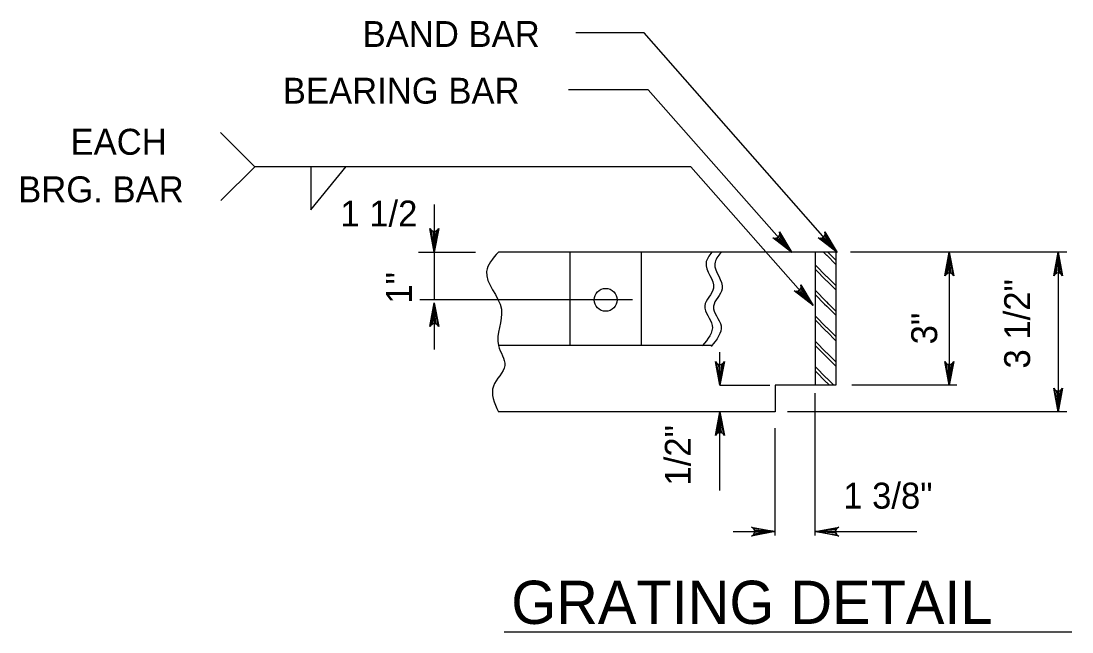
# Model space of a CAD drawing. Extents: x -0.3 to 6.9, y -6.5 to 3.5.
# Drawn here: x 3.745 to 6.178, y -4.783 to -3.37 of the extents above; entities that cross this region are included whole.
import ezdxf

# ---------------------------------------------------------------- set-up
doc = ezdxf.new("R2010")
doc.units = 0
for name, color, linetype in [('DETL-DIMS', 7, 'Continuous'), ('DETL-LINE', 7, 'Continuous'), ('DETL-NOTE', 7, 'Continuous'), ('DETL-PATT', 7, 'Continuous'), ('DETL-TITL', 7, 'Continuous')]:
    doc.layers.add(name, color=color, linetype=linetype)

msp = doc.modelspace()

# ---------------------------------------------------------------- linework, layer by layer
at = {"layer": 'DETL-DIMS'}
for p, q in [((5.188, -3.3971), (5.0297, -3.3971)), ((5.6347, -3.9053), (5.188, -3.3971)), ((5.1968, -3.5285), (5.0123, -3.5285)), ((5.5296, -3.9053), (5.1968, -3.5285)), ((4.2859, -3.7067), (4.2066, -3.6274)), ((4.2859, -3.7067), (4.2074, -3.7852)), ((5.296, -3.7067), (4.2859, -3.7067)), ((4.4154, -3.8066), (4.4978, -3.7065)), ((4.4154, -3.7067), (4.4154, -3.8066)), ((5.5792, -4.028), (5.296, -3.7067)), ((4.7016, -3.7941), (4.7016, -3.9044)), ((4.6654, -3.9044), (4.7968, -3.9044)), ((4.7016, -3.9044), (4.7016, -4.0147)), ((6.1668, -3.9044), (5.6655, -3.9044)), ((5.8942, -3.9044), (5.8942, -4.2124)), ((6.1463, -3.9044), (6.1463, -4.2737)), ((5.1605, -4.0147), (4.6681, -4.0147)), ((4.7016, -4.0218), (4.7016, -4.13)), ((5.3632, -4.2124), (5.3632, -4.1361)), ((5.3632, -4.2124), (5.4785, -4.2124)), ((5.5833, -4.5597), (5.5833, -4.231)), ((5.9116, -4.2124), (5.6686, -4.2124)), ((5.3632, -4.456), (5.3632, -4.2737)), ((6.1668, -4.2737), (5.5197, -4.2737)), ((5.4914, -4.5597), (5.4914, -4.3114)), ((5.3938, -4.5509), (5.4914, -4.5509)), ((5.5833, -4.5509), (5.8191, -4.5509))]:
    msp.add_line(p, q, dxfattribs=at)
for points in [[(4.7016, -3.9044), (4.6914, -3.8496), (4.6943, -3.8538), (4.698, -3.856), (4.7016, -3.8566), (4.7053, -3.856), (4.709, -3.8538), (4.7119, -3.8496), (4.7016, -3.9044), (4.709, -3.8538), (4.7053, -3.856), (4.7016, -3.9044), (4.7016, -3.8566), (4.698, -3.856), (4.7016, -3.9044), (4.6943, -3.8538)], [(5.5296, -3.9053), (5.4856, -3.8711), (5.4906, -3.8723), (5.4947, -3.8715), (5.4979, -3.8695), (5.5003, -3.8666), (5.5016, -3.8625), (5.501, -3.8574), (5.5296, -3.9053), (5.5016, -3.8625), (5.5003, -3.8666), (5.5296, -3.9053), (5.4979, -3.8695), (5.4947, -3.8715), (5.5296, -3.9053), (5.4906, -3.8723)], [(5.6347, -3.9053), (5.5907, -3.8709), (5.5957, -3.8722), (5.5999, -3.8714), (5.6031, -3.8694), (5.6055, -3.8665), (5.6068, -3.8625), (5.6062, -3.8574), (5.6347, -3.9053), (5.6068, -3.8625), (5.6055, -3.8665), (5.6347, -3.9053), (5.6031, -3.8694), (5.5999, -3.8714), (5.6347, -3.9053), (5.5957, -3.8722)], [(5.8942, -3.9044), (5.9045, -3.9592), (5.9016, -3.955), (5.8979, -3.9528), (5.8942, -3.9522), (5.8906, -3.9528), (5.8869, -3.955), (5.8839, -3.9592), (5.8942, -3.9044), (5.8869, -3.955), (5.8906, -3.9528), (5.8942, -3.9044), (5.8942, -3.9522), (5.8979, -3.9528), (5.8942, -3.9044), (5.9016, -3.955)], [(5.8942, -3.9044), (5.9045, -3.9592), (5.9016, -3.955), (5.8979, -3.9528), (5.8942, -3.9522), (5.8906, -3.9528), (5.8869, -3.955), (5.8839, -3.9592), (5.8942, -3.9044), (5.8869, -3.955), (5.8906, -3.9528), (5.8942, -3.9044), (5.8942, -3.9522), (5.8979, -3.9528), (5.8942, -3.9044), (5.9016, -3.955)], [(6.1463, -3.9044), (6.1566, -3.9592), (6.1537, -3.955), (6.15, -3.9528), (6.1463, -3.9522), (6.1427, -3.9528), (6.139, -3.955), (6.1361, -3.9592), (6.1463, -3.9044), (6.139, -3.955), (6.1427, -3.9528), (6.1463, -3.9044), (6.1463, -3.9522), (6.15, -3.9528), (6.1463, -3.9044), (6.1537, -3.955)], [(5.5792, -4.028), (5.5352, -3.9937), (5.5402, -3.9949), (5.5444, -3.9941), (5.5476, -3.9922), (5.5499, -3.9893), (5.5512, -3.9852), (5.5507, -3.9801), (5.5792, -4.028), (5.5512, -3.9852), (5.5499, -3.9893), (5.5792, -4.028), (5.5476, -3.9922), (5.5444, -3.9941), (5.5792, -4.028), (5.5402, -3.9949)], [(4.7016, -4.0218), (4.7119, -4.0766), (4.709, -4.0724), (4.7053, -4.0702), (4.7016, -4.0696), (4.698, -4.0702), (4.6943, -4.0724), (4.6914, -4.0766), (4.7016, -4.0218), (4.6943, -4.0724), (4.698, -4.0702), (4.7016, -4.0218), (4.7016, -4.0696), (4.7053, -4.0702), (4.7016, -4.0218), (4.709, -4.0724)], [(5.3632, -4.2124), (5.3529, -4.1576), (5.3558, -4.1618), (5.3595, -4.164), (5.3632, -4.1646), (5.3668, -4.164), (5.3705, -4.1618), (5.3734, -4.1576), (5.3632, -4.2124), (5.3705, -4.1618), (5.3668, -4.164), (5.3632, -4.2124), (5.3632, -4.1646), (5.3595, -4.164), (5.3632, -4.2124), (5.3558, -4.1618)], [(5.3632, -4.2124), (5.3529, -4.1576), (5.3558, -4.1618), (5.3595, -4.164), (5.3632, -4.1646), (5.3668, -4.164), (5.3705, -4.1618), (5.3734, -4.1576), (5.3632, -4.2124), (5.3705, -4.1618), (5.3668, -4.164), (5.3632, -4.2124), (5.3632, -4.1646), (5.3595, -4.164), (5.3632, -4.2124), (5.3558, -4.1618)], [(5.8942, -4.2124), (5.8839, -4.1576), (5.8869, -4.1618), (5.8906, -4.164), (5.8942, -4.1646), (5.8979, -4.164), (5.9016, -4.1618), (5.9045, -4.1576), (5.8942, -4.2124), (5.9016, -4.1618), (5.8979, -4.164), (5.8942, -4.2124), (5.8942, -4.1646), (5.8906, -4.164), (5.8942, -4.2124), (5.8869, -4.1618)], [(5.8942, -4.2124), (5.8839, -4.1576), (5.8869, -4.1618), (5.8906, -4.164), (5.8942, -4.1646), (5.8979, -4.164), (5.9016, -4.1618), (5.9045, -4.1576), (5.8942, -4.2124), (5.9016, -4.1618), (5.8979, -4.164), (5.8942, -4.2124), (5.8942, -4.1646), (5.8906, -4.164), (5.8942, -4.2124), (5.8869, -4.1618)], [(6.1463, -4.2737), (6.1361, -4.2189), (6.139, -4.2231), (6.1427, -4.2253), (6.1463, -4.2259), (6.15, -4.2253), (6.1537, -4.2231), (6.1566, -4.2189), (6.1463, -4.2737), (6.1537, -4.2231), (6.15, -4.2253), (6.1463, -4.2737), (6.1463, -4.2259), (6.1427, -4.2253), (6.1463, -4.2737), (6.139, -4.2231)], [(5.3632, -4.2737), (5.3734, -4.3286), (5.3705, -4.3243), (5.3668, -4.3222), (5.3632, -4.3215), (5.3595, -4.3222), (5.3558, -4.3243), (5.3529, -4.3286), (5.3632, -4.2737), (5.3558, -4.3243), (5.3595, -4.3222), (5.3632, -4.2737), (5.3632, -4.3215), (5.3668, -4.3222), (5.3632, -4.2737), (5.3705, -4.3243)], [(5.4914, -4.5509), (5.4366, -4.5612), (5.4408, -4.5582), (5.443, -4.5546), (5.4436, -4.5509), (5.443, -4.5472), (5.4408, -4.5435), (5.4366, -4.5406), (5.4914, -4.5509), (5.4408, -4.5435), (5.443, -4.5472), (5.4914, -4.5509), (5.4436, -4.5509), (5.443, -4.5546), (5.4914, -4.5509), (5.4408, -4.5582)], [(5.4914, -4.5509), (5.4366, -4.5612), (5.4408, -4.5582), (5.443, -4.5546), (5.4436, -4.5509), (5.443, -4.5472), (5.4408, -4.5435), (5.4366, -4.5406), (5.4914, -4.5509), (5.4408, -4.5435), (5.443, -4.5472), (5.4914, -4.5509), (5.4436, -4.5509), (5.443, -4.5546), (5.4914, -4.5509), (5.4408, -4.5582)], [(5.5833, -4.5509), (5.6381, -4.5406), (5.6339, -4.5435), (5.6317, -4.5472), (5.6311, -4.5509), (5.6317, -4.5546), (5.6339, -4.5582), (5.6381, -4.5612), (5.5833, -4.5509), (5.6339, -4.5582), (5.6317, -4.5546), (5.5833, -4.5509), (5.6311, -4.5509), (5.6317, -4.5472), (5.5833, -4.5509), (5.6339, -4.5435)]]:
    msp.add_lwpolyline(points, dxfattribs=at)
at = {"layer": 'DETL-LINE'}
for p, q in [((5.6315, -3.9044), (4.8501, -3.9044)), ((5.0164, -4.1207), (5.0164, -3.9044)), ((5.1816, -4.1207), (5.1816, -3.9044)), ((5.5833, -3.9044), (5.5833, -4.2124)), ((5.6315, -3.9044), (5.6315, -4.2124)), ((5.3434, -4.1207), (4.8501, -4.1207)), ((5.6315, -4.2124), (5.4914, -4.2124)), ((5.4914, -4.2124), (5.4914, -4.2737)), ((5.4914, -4.2737), (4.8501, -4.2737))]:
    msp.add_line(p, q, dxfattribs=at)
msp.add_circle((5.0985, -4.0147), 0.0264, dxfattribs=at)
for points in [[(4.8501, -3.9044), (4.8226, -3.949), (4.857, -4.0365), (4.8501, -4.1207), (4.865, -4.1664), (4.8385, -4.2142), (4.8501, -4.2737)], [(5.3445, -3.9044), (5.3309, -3.9289), (5.3484, -3.9874), (5.3278, -4.0287), (5.3452, -4.0738), (5.3222, -4.1211)], [(5.3657, -3.905), (5.3512, -3.9311), (5.3686, -3.9891), (5.3483, -4.0297), (5.3657, -4.0747), (5.3425, -4.1225)]]:
    msp.add_spline(points, degree=3, dxfattribs=at)
at = {"layer": 'DETL-PATT'}
for p, q in [((5.6052, -3.9068), (5.6028, -3.9044)), ((5.6052, -3.9068), (5.6104, -3.9119)), ((5.6315, -3.9329), (5.6104, -3.9117)), ((5.6153, -3.9068), (5.6129, -3.9044)), ((5.6315, -3.9231), (5.6153, -3.9068)), ((5.6102, -3.9607), (5.5833, -3.9339)), ((5.5833, -3.9437), (5.6102, -3.9706)), ((5.6315, -3.9819), (5.6104, -3.9607)), ((5.6315, -3.9917), (5.6104, -3.9706)), ((5.6102, -4.0196), (5.5833, -3.9927)), ((5.6052, -4.0245), (5.5833, -4.0025)), ((5.6052, -4.0245), (5.6104, -4.0296)), ((5.6153, -4.0245), (5.6104, -4.0196)), ((5.6315, -4.0505), (5.6104, -4.0294)), ((5.6315, -4.0407), (5.6153, -4.0245)), ((5.6102, -4.0784), (5.5833, -4.0515)), ((5.5833, -4.0613), (5.6102, -4.0882)), ((5.6315, -4.0996), (5.6104, -4.0784)), ((5.6315, -4.1094), (5.6104, -4.0882)), ((5.6102, -4.1372), (5.5833, -4.1103)), ((5.6052, -4.1421), (5.5833, -4.1201)), ((5.6153, -4.1421), (5.6104, -4.1372)), ((5.6052, -4.1421), (5.6104, -4.1472)), ((5.6315, -4.1682), (5.6104, -4.147)), ((5.6315, -4.1584), (5.6153, -4.1421)), ((5.6102, -4.196), (5.5833, -4.1692)), ((5.5833, -4.179), (5.6102, -4.2058)), ((5.6268, -4.2124), (5.6104, -4.196)), ((5.617, -4.2124), (5.6104, -4.2058))]:
    msp.add_line(p, q, dxfattribs=at)
at = {"layer": 'DETL-TITL'}
msp.add_line((4.8633, -4.7832), (6.1784, -4.7832), dxfattribs=at)

# ---------------------------------------------------------------- texts
at = {"layer": 'DETL-NOTE'}
for s, p in [('BAND BAR', (4.5357, -3.4296)), ('BEARING BAR', (4.3508, -3.5608)), ('EACH', (3.8592, -3.679)), ('BRG. BAR', (3.738, -3.789)), ('1 1/2', (4.4841, -3.845)), ('1 3/8"', (5.6486, -4.4978))]:
    msp.add_text(s, height=0.06, dxfattribs=at).set_placement(p)
for s, p in [('1"', (4.6499, -4.0236)), ('3 1/2"', (6.0814, -4.1737)), ('3"', (5.8662, -4.1177)), ('1/2"', (5.2956, -4.4445))]:
    msp.add_text(s, height=0.06, rotation=90, dxfattribs=at).set_placement(p)
at = {"layer": 'DETL-TITL'}
msp.add_text('GRATING DETAIL', height=0.1, dxfattribs=at).set_placement((4.8799, -4.7646))

doc.saveas('drawing.dxf')
